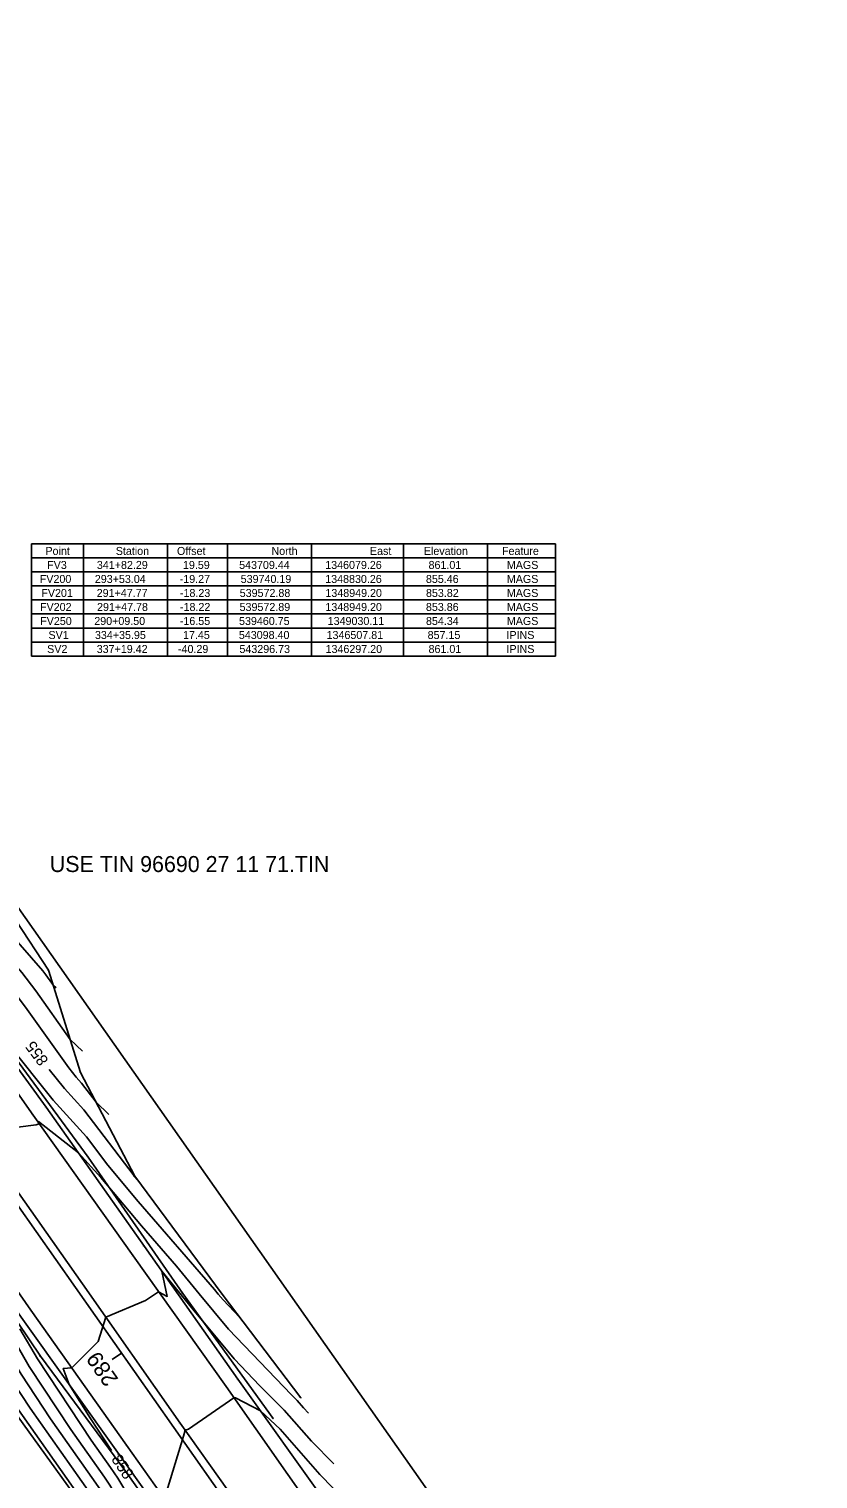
# Model space of a CAD drawing. Extents: x 1345023 to 1351589, y 535029 to 544731.
# Drawn here: x 1349090.4 to 1349228.5, y 539358.7 to 539612.3 of the extents above; entities that cross this region are included whole.
import ezdxf

# ---------------------------------------------------------------- set-up
doc = ezdxf.new("R2010")
doc.units = 0
for name, color, linetype in [('Default', 7, 'Continuous'), ('DT_X_Contour_Major', 7, 'Continuous'), ('DT_X_Contour_Minor', 7, 'Continuous'), ('GE_X_CL_20', 7, 'Continuous'), ('PV_X_EOP', 7, 'Continuous'), ('PV_X_Shoulder', 7, 'Continuous'), ('RD_X_GR_Lt', 7, 'Continuous'), ('RW_X_CL_20', 7, 'Continuous'), ('RW_X_Esmt_SH', 7, 'Continuous'), ('SV_X_Center_of_Pavt', 7, 'Continuous'), ('SV_X_Shot_Marker', 7, 'Continuous'), ('SV_X_Text', 7, 'Continuous'), ('SV_X_Text_Elevation', 7, 'Continuous'), ('SV_X_Text_Name', 7, 'Continuous'), ('SV_X_Toe_of_Slope', 7, 'Continuous')]:
    doc.layers.add(name, color=color, linetype=linetype)

msp = doc.modelspace()

# ---------------------------------------------------------------- linework, layer by layer
at = {"layer": 'Default'}
msp.add_circle((1349064.59, 539442.56), 239.67, dxfattribs=at)
msp.add_circle((1349064.59, 539442.56), 239.67, dxfattribs=at)
at = {"layer": 'DT_X_Contour_Major'}
for points in [[(1349093.98, 539430.32), (1349096.65, 539426.95), (1349100.05, 539423.22), (1349108.81, 539411.69), (1349108.94, 539411.54), (1349109.36, 539411.04)], [(1349071.31, 539405.13), (1349072.17, 539403.92), (1349076.08, 539398.12), (1349081.55, 539389.34), (1349087.35, 539379.88), (1349089.05, 539376.99), (1349094.21, 539369.19), (1349102.54, 539357.34), (1349103.21, 539356.36), (1349107.96, 539348.43), (1349116.82, 539333.05), (1349116.88, 539332.92), (1349118.46, 539329.8), (1349123.72, 539320.84)]]:
    msp.add_lwpolyline(points, dxfattribs=at)
at = {"layer": 'DT_X_Contour_Minor'}
for points in [[(1349053.01, 539493.76), (1349057.61, 539487.16), (1349063.86, 539481.34), (1349066.02, 539479.19), (1349073.84, 539471.8), (1349077.15, 539467.32), (1349085.64, 539456.15), (1349086.51, 539454.84), (1349092.85, 539447.57), (1349093.38, 539446.87), (1349094.7, 539445.02), (1349095.16, 539444.58)], [(1349049.76, 539491.71), (1349057.47, 539480.67), (1349059.92, 539478.38), (1349063.19, 539475.13), (1349067.19, 539471.36), (1349074.55, 539461.37), (1349078.88, 539455.67), (1349082.08, 539450.85), (1349085.46, 539446.97), (1349089.81, 539441.23), (1349097.38, 539430.59), (1349098.67, 539428.97), (1349099.62, 539427.92), (1349102.17, 539424.57), (1349104.41, 539422.44)], [(1349052.46, 539491.2), (1349057.54, 539483.91), (1349061.89, 539479.86), (1349064.61, 539477.16), (1349070.52, 539471.58), (1349075.85, 539464.35), (1349082.26, 539455.91), (1349084.29, 539452.85), (1349089.15, 539447.27), (1349091.6, 539444.05), (1349097.66, 539435.53), (1349099.78, 539433.51)], [(1349083.75, 539438.9), (1349086.25, 539435.59), (1349086.8, 539434.81), (1349094.64, 539424.92), (1349100.47, 539418.52), (1349104.23, 539413.57), (1349109.53, 539407.23), (1349122.89, 539391.8), (1349123.55, 539391), (1349124.4, 539389.98), (1349127.24, 539387)], [(1349139.34, 539370.19), (1349138.44, 539371.11), (1349137.33, 539372.37), (1349136.34, 539373.36), (1349125.35, 539384.85), (1349120.18, 539391.06), (1349116.23, 539395.88), (1349110.13, 539402.93), (1349103.02, 539411.42), (1349099.07, 539415.74), (1349092.11, 539421.19), (1349092.24, 539420.81), (1349091.66, 539420.62), (1349085.21, 539419.81)], [(1349065.45, 539418.32), (1349070.2, 539410.2), (1349072.46, 539406.98), (1349077.47, 539399.56), (1349084.48, 539388.3), (1349088.1, 539382.4), (1349090.49, 539378.33), (1349097.77, 539367.33), (1349103.63, 539359.01), (1349104.59, 539357.6), (1349111.41, 539346.2), (1349118.07, 539334.64), (1349118.18, 539334.37), (1349121.41, 539327.99), (1349132.19, 539309.63)], [(1349071.21, 539401.79), (1349071.87, 539400.86), (1349074.68, 539396.69), (1349078.62, 539390.37), (1349086.6, 539377.36), (1349087.6, 539375.65), (1349090.65, 539371.04), (1349101.46, 539355.68), (1349101.84, 539355.12), (1349104.51, 539350.66), (1349115.11, 539332.28)], [(1349143.76, 539361.3), (1349139.86, 539365.28), (1349135.1, 539370.71), (1349130.83, 539374.98), (1349126.3, 539379.71), (1349119.09, 539388.39), (1349113.67, 539395), (1349114.63, 539390.61), (1349113.07, 539391.43), (1349110.83, 539389.86), (1349103.88, 539386.97), (1349102.55, 539382.72), (1349097.91, 539378.12), (1349096.42, 539378.01), (1349097.44, 539375.22), (1349101.17, 539369.24), (1349104.87, 539363.66)], [(1349088.85, 539384.92), (1349091.94, 539379.66), (1349101.33, 539365.48), (1349104.71, 539360.68), (1349105.96, 539358.83), (1349114.86, 539343.97)], [(1349100.38, 539354.01), (1349087.09, 539372.9)], [(1349148.18, 539352.41), (1349141.29, 539359.45), (1349134.35, 539367.36), (1349130.94, 539370.56), (1349126.57, 539372.87), (1349126.27, 539372.86), (1349118.34, 539367.4), (1349117.73, 539367.19), (1349117.47, 539366.17), (1349114.13, 539355.23), (1349114.67, 539352.62), (1349114.85, 539350.79), (1349117.18, 539347.04), (1349121.47, 539340.01), (1349121.76, 539339.52), (1349121.82, 539339.41), (1349122.09, 539338.72), (1349122.21, 539338.48)]]:
    msp.add_lwpolyline(points, dxfattribs=at)
at = {"layer": 'GE_X_CL_20'}
msp.add_line((1349106.63, 539380.69), (1349105, 539379.54), dxfattribs=at)
at = {"layer": 'PV_X_EOP'}
for points in [[(1349216.36, 539247.17), (1349201.67, 539267.22), (1349187.22, 539287.89), (1349171.76, 539309.15), (1349156.32, 539330.74), (1349140.9, 539352.07), (1349124.9, 539374.82), (1349108.63, 539397.68), (1349091.17, 539422.31), (1349075.29, 539444.85), (1349058.27, 539468.96), (1349041.54, 539492.94), (1349024.5, 539517.56), (1349006.82, 539542.79), (1348989.6, 539567.23), (1348974.2, 539589), (1348964, 539603.87)], [(1348963.82, 539568.64), (1348978.89, 539547.32), (1348994.51, 539524.89), (1349010.43, 539502.72), (1349026.32, 539479.94), (1349042.26, 539457.26), (1349058.17, 539434.76), (1349074.58, 539411.35), (1349090.76, 539388.22), (1349107.5, 539364.57), (1349124.37, 539340.8), (1349149.03, 539306.44), (1349166.16, 539282.37), (1349186.61, 539254.2), (1349199.44, 539235.88)]]:
    msp.add_lwpolyline(points, dxfattribs=at)
at = {"layer": 'PV_X_Shoulder'}
for points in [[(1349218.45, 539248.64), (1349204.11, 539269.14), (1349189.37, 539289.68), (1349173.79, 539311.27), (1349158.01, 539332.61), (1349142.54, 539354.33), (1349126.97, 539376.12), (1349110.63, 539399.31), (1349093.45, 539423.72), (1349077.01, 539446.28), (1349060.24, 539470.89), (1349043.33, 539494.64), (1349026.62, 539518.81), (1349009.16, 539544.42), (1348992, 539568.54), (1348976.04, 539590.68), (1348965.68, 539605.25)], [(1348962, 539567.08), (1348977.2, 539545.66), (1348992.86, 539523.75), (1349008.54, 539501.01), (1349024.74, 539478.38), (1349040.53, 539455.35), (1349056.49, 539433.07), (1349072.75, 539409.98), (1349089.35, 539386.59), (1349106.19, 539362.95), (1349122.85, 539339.57), (1349147.29, 539304.88), (1349164.42, 539281.07), (1349184.44, 539252.65), (1349197.28, 539234.25)]]:
    msp.add_lwpolyline(points, dxfattribs=at)
at = {"layer": 'RD_X_GR_Lt'}
for points in [[(1348971.39, 539601.4), (1348985.64, 539578.36), (1349000.05, 539557.85), (1349014.72, 539537.97), (1349028.89, 539517.34), (1349042.99, 539496.35), (1349057.38, 539476.47), (1349071.84, 539455.17), (1349085.97, 539435.15), (1349100.79, 539414.98), (1349117.34, 539391.11), (1349133.15, 539369.26)], [(1349193.63, 539235), (1349179.2, 539257.78), (1349165, 539278.49), (1349150.55, 539298.84), (1349135.96, 539319.09), (1349121.86, 539339.46), (1349107.31, 539360.04), (1349092.47, 539380.15), (1349078.54, 539400.65), (1349064.05, 539421.16), (1349049.42, 539441.63), (1349034.67, 539461.66), (1349020.71, 539482.17), (1349006.3, 539502.6), (1348991.9, 539523.29), (1348977.37, 539543.25), (1348960.47, 539564.16)]]:
    msp.add_lwpolyline(points, dxfattribs=at)
at = {"layer": 'RW_X_CL_20'}
msp.add_line((1349456.54, 538883.15), (1348162.36, 540723.41), dxfattribs=at)
msp.add_line((1349456.54, 538883.15), (1348162.36, 540723.41), dxfattribs=at)
at = {"layer": 'RW_X_Esmt_SH'}
msp.add_line((1349481.08, 538900.4), (1348186.89, 540740.69), dxfattribs=at)
at = {"layer": 'SV_X_Center_of_Pavt'}
msp.add_lwpolyline([(1348956.29, 539596.18), (1348972.49, 539573.75), (1348989.34, 539550.27), (1349007.81, 539523.61), (1349026.02, 539497.71), (1349045.23, 539470.25), (1349064.59, 539442.56), (1349081.75, 539418.35), (1349099.8, 539392.79), (1349116.87, 539368.41), (1349133.78, 539344.64), (1349155.85, 539314.05), (1349175.72, 539286.38), (1349192.81, 539262.11), (1349207.82, 539240.9)], dxfattribs=at)
at = {"layer": 'SV_X_Shot_Marker'}
for p, q in [((1349093.85, 539447.66), (1349093.9, 539447.66)), ((1349093.87, 539447.68), (1349093.87, 539447.63)), ((1349093.87, 539447.66), (1349093.87, 539447.66)), ((1349099.43, 539429.77), (1349099.48, 539429.77)), ((1349099.46, 539429.79), (1349099.46, 539429.74)), ((1349099.46, 539429.77), (1349099.46, 539429.77)), ((1349093.43, 539423.72), (1349093.47, 539423.72)), ((1349093.45, 539423.75), (1349093.45, 539423.7)), ((1349093.45, 539423.72), (1349093.45, 539423.72)), ((1349091.14, 539422.31), (1349091.19, 539422.31)), ((1349091.17, 539422.34), (1349091.17, 539422.29)), ((1349091.17, 539422.31), (1349091.17, 539422.31)), ((1349100.76, 539414.98), (1349100.81, 539414.98)), ((1349100.79, 539415.01), (1349100.79, 539414.96)), ((1349100.79, 539414.98), (1349100.79, 539414.98)), ((1349108.9, 539411.64), (1349108.95, 539411.64)), ((1349108.92, 539411.67), (1349108.92, 539411.62)), ((1349108.92, 539411.64), (1349108.92, 539411.64)), ((1349110.6, 539399.31), (1349110.65, 539399.31)), ((1349110.63, 539399.34), (1349110.63, 539399.29)), ((1349110.63, 539399.31), (1349110.63, 539399.31)), ((1349108.6, 539397.68), (1349108.65, 539397.68)), ((1349108.63, 539397.7), (1349108.63, 539397.65)), ((1349108.63, 539397.68), (1349108.63, 539397.68)), ((1349099.77, 539392.79), (1349099.82, 539392.79)), ((1349099.8, 539392.82), (1349099.8, 539392.77)), ((1349099.8, 539392.79), (1349099.8, 539392.79)), ((1349117.32, 539391.11), (1349117.37, 539391.11)), ((1349117.34, 539391.13), (1349117.34, 539391.08)), ((1349117.34, 539391.11), (1349117.34, 539391.11)), ((1349124.18, 539390.99), (1349124.23, 539390.99)), ((1349124.21, 539391.02), (1349124.21, 539390.97)), ((1349124.21, 539390.99), (1349124.21, 539390.99)), ((1349090.73, 539388.22), (1349090.78, 539388.22)), ((1349090.76, 539388.24), (1349090.76, 539388.19)), ((1349090.76, 539388.22), (1349090.76, 539388.22)), ((1349092.44, 539380.15), (1349092.49, 539380.15)), ((1349092.47, 539380.18), (1349092.47, 539380.13)), ((1349092.47, 539380.15), (1349092.47, 539380.15)), ((1349126.94, 539376.12), (1349126.99, 539376.12)), ((1349126.97, 539376.14), (1349126.97, 539376.09)), ((1349126.97, 539376.12), (1349126.97, 539376.12)), ((1349124.87, 539374.82), (1349124.92, 539374.82)), ((1349124.9, 539374.84), (1349124.9, 539374.79)), ((1349124.9, 539374.82), (1349124.9, 539374.82)), ((1349137.98, 539372.88), (1349138.03, 539372.88)), ((1349138, 539372.9), (1349138, 539372.85)), ((1349138, 539372.88), (1349138, 539372.88)), ((1349116.84, 539368.41), (1349116.89, 539368.41)), ((1349116.87, 539368.43), (1349116.87, 539368.38)), ((1349116.87, 539368.41), (1349116.87, 539368.41)), ((1349133.12, 539369.26), (1349133.17, 539369.26)), ((1349133.15, 539369.28), (1349133.15, 539369.23)), ((1349133.15, 539369.26), (1349133.15, 539369.26)), ((1349106.16, 539362.95), (1349106.21, 539362.95)), ((1349106.19, 539362.97), (1349106.19, 539362.92)), ((1349106.19, 539362.95), (1349106.19, 539362.95)), ((1349107.48, 539364.57), (1349107.53, 539364.57)), ((1349107.5, 539364.59), (1349107.5, 539364.54)), ((1349107.5, 539364.57), (1349107.5, 539364.57)), ((1349107.29, 539360.04), (1349107.34, 539360.04)), ((1349107.31, 539360.07), (1349107.31, 539360.02)), ((1349107.31, 539360.04), (1349107.31, 539360.04))]:
    msp.add_line(p, q, dxfattribs=at)
at = {"layer": 'SV_X_Text'}
for p, q in [((1349090.85, 539522.23), (1349182.55, 539522.23)), ((1349090.85, 539522.23), (1349090.85, 539502.63)), ((1349099.95, 539522.23), (1349099.95, 539502.63)), ((1349114.65, 539522.23), (1349114.65, 539502.63)), ((1349125.15, 539522.23), (1349125.15, 539502.63)), ((1349139.85, 539522.23), (1349139.85, 539502.63)), ((1349155.95, 539522.23), (1349155.95, 539502.63)), ((1349170.65, 539522.23), (1349170.65, 539502.63)), ((1349182.55, 539522.23), (1349182.55, 539502.63)), ((1349182.55, 539522.23), (1349182.55, 539502.63)), ((1349090.85, 539519.78), (1349182.55, 539519.78)), ((1349090.85, 539517.33), (1349182.55, 539517.33)), ((1349090.85, 539517.33), (1349182.55, 539517.33)), ((1349090.85, 539517.33), (1349182.55, 539517.33)), ((1349090.85, 539517.33), (1349182.55, 539517.33)), ((1349090.85, 539517.33), (1349182.55, 539517.33)), ((1349090.85, 539517.33), (1349182.55, 539517.33)), ((1349090.85, 539517.33), (1349182.55, 539517.33)), ((1349090.85, 539514.88), (1349182.55, 539514.88)), ((1349090.85, 539514.88), (1349182.55, 539514.88)), ((1349090.85, 539514.88), (1349182.55, 539514.88)), ((1349090.85, 539514.88), (1349182.55, 539514.88)), ((1349090.85, 539514.88), (1349182.55, 539514.88)), ((1349090.85, 539514.88), (1349182.55, 539514.88)), ((1349090.85, 539514.88), (1349182.55, 539514.88)), ((1349090.85, 539512.43), (1349182.55, 539512.43)), ((1349090.85, 539512.43), (1349182.55, 539512.43)), ((1349090.85, 539512.43), (1349182.55, 539512.43)), ((1349090.85, 539512.43), (1349182.55, 539512.43)), ((1349090.85, 539512.43), (1349182.55, 539512.43)), ((1349090.85, 539512.43), (1349182.55, 539512.43)), ((1349090.85, 539512.43), (1349182.55, 539512.43)), ((1349090.85, 539509.98), (1349182.55, 539509.98)), ((1349090.85, 539509.98), (1349182.55, 539509.98)), ((1349090.85, 539509.98), (1349182.55, 539509.98)), ((1349090.85, 539509.98), (1349182.55, 539509.98)), ((1349090.85, 539509.98), (1349182.55, 539509.98)), ((1349090.85, 539509.98), (1349182.55, 539509.98)), ((1349090.85, 539509.98), (1349182.55, 539509.98)), ((1349090.85, 539507.53), (1349182.55, 539507.53)), ((1349090.85, 539507.53), (1349182.55, 539507.53)), ((1349090.85, 539507.53), (1349182.55, 539507.53)), ((1349090.85, 539507.53), (1349182.55, 539507.53)), ((1349090.85, 539507.53), (1349182.55, 539507.53)), ((1349090.85, 539507.53), (1349182.55, 539507.53)), ((1349090.85, 539507.53), (1349182.55, 539507.53)), ((1349090.85, 539505.08), (1349182.55, 539505.08)), ((1349090.85, 539505.08), (1349182.55, 539505.08)), ((1349090.85, 539505.08), (1349182.55, 539505.08)), ((1349090.85, 539505.08), (1349182.55, 539505.08)), ((1349090.85, 539505.08), (1349182.55, 539505.08)), ((1349090.85, 539505.08), (1349182.55, 539505.08)), ((1349090.85, 539505.08), (1349182.55, 539505.08)), ((1349090.85, 539502.63), (1349182.55, 539502.63)), ((1349090.85, 539502.63), (1349182.55, 539502.63)), ((1349090.85, 539502.63), (1349182.55, 539502.63)), ((1349090.85, 539502.63), (1349182.55, 539502.63)), ((1349090.85, 539502.63), (1349182.55, 539502.63)), ((1349090.85, 539502.63), (1349182.55, 539502.63)), ((1349090.85, 539502.63), (1349182.55, 539502.63))]:
    msp.add_line(p, q, dxfattribs=at)
at = {"layer": 'SV_X_Toe_of_Slope'}
for points in [[(1349138, 539372.88), (1349124.21, 539390.99), (1349108.92, 539411.64), (1349099.46, 539429.77), (1349093.87, 539447.66), (1349088.16, 539456.33), (1349079.27, 539472.17), (1349071.54, 539487.11)], [(1349027.74, 539448.29), (1349036.38, 539438.91), (1349045.57, 539427.4), (1349057.51, 539411.27), (1349071.11, 539393.02), (1349085.51, 539373.72), (1349100.06, 539353.53), (1349115.63, 539331.53), (1349133.76, 539307.56), (1349148.08, 539286.92), (1349162.68, 539266.05), (1349188.62, 539232.38)]]:
    msp.add_lwpolyline(points, dxfattribs=at)

# ---------------------------------------------------------------- texts
at = {"layer": 'Default'}
for s, height, p in [('FV3', 1.4, (1349093.61, 539517.86)), ('341+82.29', 1.4, (1349102.31, 539517.86)), ('19.59', 1.4, (1349117.37, 539517.86)), ('543709.44', 1.4, (1349127.2, 539517.86)), ('1346079.26', 1.4, (1349142.26, 539517.86)), ('861.01', 1.4, (1349160.34, 539517.86)), ('MAGS', 1.4, (1349174.04, 539517.86)), ('FV200', 1.4, (1349092.32, 539515.41)), ('293+53.04', 1.4, (1349101.95, 539515.41)), ('-19.27', 1.4, (1349116.8, 539515.41)), ('539740.19', 1.4, (1349127.47, 539515.41)), ('1348830.26', 1.4, (1349142.26, 539515.41)), ('855.46', 1.4, (1349159.88, 539515.41)), ('MAGS', 1.4, (1349174.04, 539515.41)), ('FV201', 1.4, (1349092.59, 539512.96)), ('291+47.77', 1.4, (1349102.28, 539512.96)), ('-18.23', 1.4, (1349116.84, 539512.96)), ('539572.88', 1.4, (1349127.3, 539512.96)), ('1348949.20', 1.4, (1349142.29, 539512.96)), ('853.82', 1.4, (1349159.89, 539512.96)), ('MAGS', 1.4, (1349174.04, 539512.96)), ('FV202', 1.4, (1349092.36, 539510.51)), ('291+47.78', 1.4, (1349102.34, 539510.51)), ('-18.22', 1.4, (1349116.85, 539510.51)), ('539572.89', 1.4, (1349127.28, 539510.51)), ('1348949.20', 1.4, (1349142.29, 539510.51)), ('853.86', 1.4, (1349159.88, 539510.51)), ('MAGS', 1.4, (1349174.04, 539510.51)), ('FV250', 1.4, (1349092.39, 539508.06)), ('290+09.50', 1.4, (1349101.85, 539508.06)), ('-16.55', 1.4, (1349116.82, 539508.06)), ('539460.75', 1.4, (1349127.18, 539508.06)), ('1349030.11', 1.4, (1349142.69, 539508.06)), ('854.34', 1.4, (1349159.89, 539508.06)), ('MAGS', 1.4, (1349174.04, 539508.06)), ('SV1', 1.4, (1349093.84, 539505.61)), ('334+35.95', 1.4, (1349101.97, 539505.61)), ('17.45', 1.4, (1349117.38, 539505.61)), ('543098.40', 1.4, (1349127.15, 539505.61)), ('1346507.81', 1.4, (1349142.5, 539505.61)), ('857.15', 1.4, (1349160.18, 539505.61)), ('IPINS', 1.4, (1349173.97, 539505.61)), ('SV2', 1.4, (1349093.61, 539503.16)), ('337+19.42', 1.4, (1349102.28, 539503.16)), ('-40.29', 1.4, (1349116.5, 539503.16)), ('543296.73', 1.4, (1349127.25, 539503.16)), ('1346297.20', 1.4, (1349142.32, 539503.16)), ('861.01', 1.4, (1349160.34, 539503.16)), ('IPINS', 1.4, (1349173.97, 539503.16)), ('USE TIN 96690 27 11 71.TIN', 2.8, (1349094.07, 539464.84))]:
    msp.add_text(s, height=height, dxfattribs=at).set_placement(p)
at = {"layer": 'DT_X_Contour_Major'}
msp.add_text('855', height=2, rotation=126.9246, dxfattribs=at).set_placement((1349093.93, 539431.92))
at = {"layer": 'DT_X_Contour_Minor'}
msp.add_text('858', height=2, rotation=303.5621, dxfattribs=at).set_placement((1349104.75, 539362.13))
at = {"layer": 'GE_X_CL_20'}
msp.add_text('289', height=2.8, rotation=125.1169, dxfattribs=at).set_placement((1349106.17, 539376.14))
at = {"layer": 'SV_X_Text'}
for s, p in [('Point', (1349093.31, 539520.31)), ('Station', (1349105.62, 539520.31)), ('Offset', (1349116.32, 539520.31)), ('North', (1349132.85, 539520.31)), ('East', (1349150.08, 539520.31)), ('Elevation', (1349159.52, 539520.31)), ('Feature', (1349173.19, 539520.31))]:
    msp.add_text(s, height=1.4, dxfattribs=at).set_placement(p)
at = {"layer": 'SV_X_Text_Elevation'}
for s, p in [('851.72', (1349093.62, 539447.59)), ('853.61', (1349099.2, 539429.7)), ('856.59', (1349093.17, 539423.66)), ('856.96', (1349090.88, 539422.25)), ('856.75', (1349100.51, 539414.92)), ('854.98', (1349108.64, 539411.58)), ('857.84', (1349110.35, 539399.25)), ('857.66', (1349108.34, 539397.62)), ('857.71', (1349099.54, 539392.73)), ('857.85', (1349117.06, 539391.05)), ('855.80', (1349123.92, 539390.93)), ('857.61', (1349090.5, 539388.16)), ('857.37', (1349092.19, 539380.09)), ('858.70', (1349126.68, 539376.06)), ('858.91', (1349124.64, 539374.76)), ('856.70', (1349137.72, 539372.81)), ('858.94', (1349116.58, 539368.35)), ('858.87', (1349132.87, 539369.2)), ('858.37', (1349105.9, 539362.89)), ('858.53', (1349107.22, 539364.51)), ('857.98', (1349107.03, 539359.98))]:
    msp.add_text(s, height=0.06, dxfattribs=at).set_placement(p)
at = {"layer": 'SV_X_Text_Name'}
for s, p in [('FV2142', (1349093.6, 539447.66)), ('FV2141', (1349099.21, 539429.77)), ('FV2075', (1349093.15, 539423.72)), ('FV2076', (1349090.86, 539422.31)), ('FV2056', (1349100.48, 539414.98)), ('FV2140', (1349108.64, 539411.64)), ('FV2074', (1349110.33, 539399.31)), ('FV2073', (1349108.33, 539397.68)), ('FV2101', (1349099.54, 539392.79)), ('FV2057', (1349117.04, 539391.11)), ('FV2139', (1349123.93, 539390.99)), ('FV2017', (1349090.48, 539388.22)), ('FV2037', (1349092.17, 539380.15)), ('FV2071', (1349126.69, 539376.12)), ('FV2072', (1349124.6, 539374.82)), ('FV2138', (1349137.73, 539372.88)), ('FV2102', (1349116.59, 539368.41)), ('FV2058', (1349132.85, 539369.26)), ('FV2019', (1349105.91, 539362.95)), ('FV2018', (1349107.23, 539364.57)), ('FV2036', (1349107.01, 539360.04))]:
    msp.add_text(s, height=0.06, dxfattribs=at).set_placement(p)

doc.saveas('drawing.dxf')
